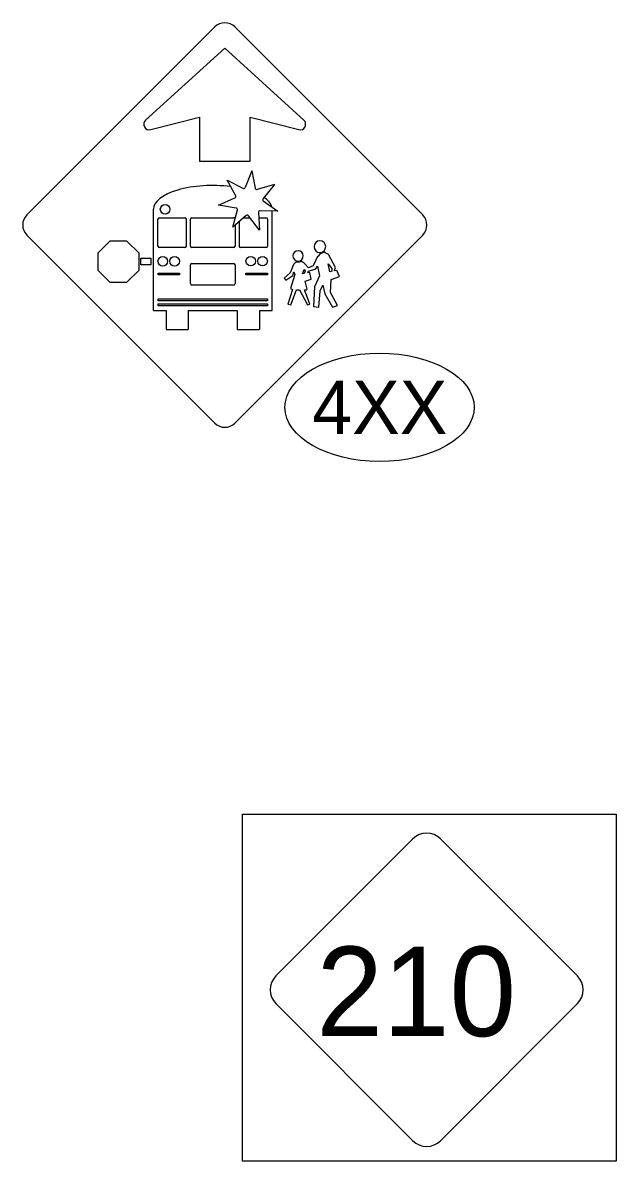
# Model space of a CAD drawing. Extents: x 1977705 to 1981198, y 827296 to 829291.
# Drawn here: x 1979110.5 to 1979241.2, y 827983.6 to 828234.2 of the extents above; entities that cross this region are included whole.
import ezdxf

# ---------------------------------------------------------------- set-up
doc = ezdxf.new("R2010")
doc.units = 0
doc.layers.add('Default', color=7, linetype='Continuous')
doc.layers.add('Level 15', color=7, linetype='Continuous')

msp = doc.modelspace()

# ---------------------------------------------------------------- linework, layer by layer
at = {"layer": 'Default'}
for p, q in [((1979172.67, 828212.53), (1979172.67, 828212.53)), ((1979160.92, 828201.62), (1979159.46, 828197.96)), ((1979160.92, 828201.62), (1979161.69, 828197.81)), ((1979157.38, 828196.13), (1979155.48, 828199.59)), ((1979155.48, 828199.59), (1979158.98, 828197.78)), ((1979165.95, 828198.6), (1979162.13, 828197.54)), ((1979165.95, 828198.6), (1979163.4, 828195.52)), ((1979153.62, 828194.04), (1979157.22, 828195.65)), ((1979157.49, 828193.44), (1979153.62, 828194.04)), ((1979163.47, 828195.02), (1979166.68, 828192.74)), ((1979139.26, 828170.89), (1979139.26, 828193.18)), ((1979140.61, 828191.3), (1979146.18, 828191.3)), ((1979147.75, 828191.3), (1979156.9, 828191.3)), ((1979156.75, 828189.24), (1979157.77, 828193.01)), ((1979159.68, 828191.8), (1979156.75, 828189.24)), ((1979159.13, 828191.3), (1979160.52, 828191.3)), ((1979162.61, 828188.56), (1979160.18, 828191.75)), ((1979162.38, 828192.49), (1979162.61, 828188.56)), ((1979162.45, 828191.3), (1979164.04, 828191.3)), ((1979166.68, 828192.74), (1979162.74, 828192.86)), ((1979165.39, 828170.89), (1979165.39, 828192.79)), ((1979140.26, 828185.07), (1979140.26, 828190.96)), ((1979146.53, 828185.07), (1979146.53, 828190.96)), ((1979147.4, 828185.07), (1979147.4, 828190.96)), ((1979157.25, 828189.68), (1979157.25, 828185.07)), ((1979158.12, 828190.44), (1979158.12, 828185.07)), ((1979164.39, 828190.96), (1979164.39, 828185.07)), ((1979129.68, 828186.15), (1979127.02, 828183.49)), ((1979133.43, 828186.15), (1979129.68, 828186.15)), ((1979136.09, 828183.49), (1979133.43, 828186.15)), ((1979146.18, 828184.72), (1979140.61, 828184.72)), ((1979156.9, 828184.72), (1979147.75, 828184.72)), ((1979164.04, 828184.72), (1979158.47, 828184.72)), ((1979127.02, 828183.49), (1979127.02, 828179.74)), ((1979136.09, 828179.74), (1979136.09, 828183.49)), ((1979171.99, 828181.61), (1979171.99, 828181.61)), ((1979172.47, 828181.3), (1979172.47, 828181.3)), ((1979127.02, 828179.74), (1979129.68, 828177.09)), ((1979133.43, 828177.09), (1979136.09, 828179.74)), ((1979169.39, 828179.17), (1979169.39, 828179.17)), ((1979170.13, 828180.99), (1979170.13, 828180.99)), ((1979172.12, 828178.93), (1979172.12, 828178.93)), ((1979172.43, 828179.88), (1979172.43, 828179.88)), ((1979172.49, 828179.02), (1979172.49, 828179.02)), ((1979172.69, 828179.54), (1979172.69, 828179.54)), ((1979129.68, 828177.09), (1979133.43, 828177.09)), ((1979168.08, 828177.97), (1979168.08, 828177.97)), ((1979168.4, 828177.58), (1979168.4, 828177.58)), ((1979139.26, 828170.89), (1979142.05, 828170.89)), ((1979142.05, 828170.89), (1979142.05, 828166.71)), ((1979146.93, 828170.89), (1979146.93, 828166.71)), ((1979146.93, 828170.89), (1979157.72, 828170.89)), ((1979157.72, 828170.89), (1979157.72, 828166.71)), ((1979162.6, 828170.89), (1979162.6, 828166.71)), ((1979162.6, 828170.89), (1979165.39, 828170.89)), ((1979142.05, 828166.71), (1979146.93, 828166.71)), ((1979157.72, 828166.71), (1979162.6, 828166.71))]:
    msp.add_line(p, q, dxfattribs=at)
for points in [[(1979152.77, 828233.3), (1979111.39, 828191.92)], [(1979198.59, 828191.92), (1979157.21, 828233.3)], [(1979172.4, 828212.78), (1979154.98, 828228.63), (1979137.55, 828212.78)], [(1979138.67, 828210.69), (1979149.44, 828213.47), (1979149.44, 828203.79), (1979155.01, 828203.79)], [(1979155.01, 828203.79), (1979160.59, 828203.79), (1979160.59, 828213.45), (1979171.28, 828210.69)], [(1979111.39, 828187.48), (1979152.77, 828146.1)], [(1979157.21, 828146.1), (1979198.59, 828187.48)], [(1979170.71, 828181.62), (1979170.13, 828180.99), (1979169.39, 828179.17), (1979168.08, 828177.97), (1979168.4, 828177.58), (1979169.99, 828178.61), (1979170.21, 828179.42), (1979170.42, 828178.78), (1979169.43, 828175.7), (1979169.86, 828175.52), (1979168.84, 828172.25), (1979169.55, 828172.12), (1979170.81, 828175.43), (1979171.47, 828175.42), (1979173.18, 828172.1), (1979173.75, 828172.3), (1979172.57, 828175.42), (1979172.7, 828175.43), (1979172.81, 828175.43), (1979172.97, 828175.46), (1979173.08, 828175.51), (1979173.16, 828175.56), (1979172.65, 828177.37), (1979174.03, 828177.75), (1979173.7, 828179.28), (1979173.27, 828179.21), (1979173.4, 828179.53), (1979175, 828180.04), (1979175.38, 828180.67), (1979175.84, 828178.51), (1979174.74, 828176.11), (1979174.55, 828171.74), (1979175.71, 828171.59), (1979175.97, 828175.19), (1979176.58, 828176.48), (1979177, 828174.59), (1979178.72, 828171.59), (1979179.8, 828171.99), (1979178.26, 828174.82), (1979178.4, 828177.74), (1979180.22, 828178.36), (1979179.68, 828179.69), (1979179.17, 828179.63), (1979179.36, 828180.38), (1979177.84, 828183.19), (1979177.06, 828183.58), (1979177.02, 828183.83), (1979176.9, 828183.87)], [(1979147.75, 828181.25), (1979156.9, 828181.25)], [(1979171.99, 828181.61), (1979171.8, 828181.74)], [(1979175.95, 828183.49), (1979175.94, 828183.29), (1979175.44, 828182.8), (1979175.42, 828182.74), (1979174.42, 828180.69), (1979173.41, 828180.25), (1979172.61, 828181.17), (1979172.47, 828181.3), (1979171.99, 828181.61)], [(1979178.55, 828179.51), (1979178.13, 828179.4), (1979177.73, 828181.14), (1979178.59, 828180.11), (1979178.55, 828179.51)], [(1979147.4, 828176.81), (1979147.4, 828180.91)], [(1979157.25, 828180.91), (1979157.25, 828176.81)], [(1979172.49, 828179.02), (1979172.12, 828178.93), (1979172.43, 828179.88), (1979172.69, 828179.54), (1979172.49, 828179.02)], [(1979156.9, 828176.46), (1979147.75, 828176.46)]]:
    msp.add_lwpolyline(points, dxfattribs=at)
for points in [[(1979138.72, 828180.92), (1979136.51, 828180.92), (1979136.51, 828182.39), (1979138.72, 828182.39)], [(1979140.27, 828179.14), (1979145.02, 828179.14), (1979145.02, 828178.73), (1979140.27, 828178.73)], [(1979159.63, 828179.14), (1979164.38, 828179.14), (1979164.38, 828178.73), (1979159.63, 828178.73)], [(1979140.27, 828173.46), (1979164.38, 828173.46), (1979164.38, 828173.05), (1979140.27, 828173.05)], [(1979140.27, 828172.35), (1979164.38, 828172.35), (1979164.38, 828171.93), (1979140.27, 828171.93)]]:
    msp.add_lwpolyline(points, close=True, dxfattribs=at)
for centre in [(1979141.83, 828193.16), (1979141.31, 828181.71), (1979143.93, 828181.71), (1979160.7, 828181.74), (1979163.31, 828181.74)]:
    msp.add_circle(centre, 1.05, dxfattribs=at)
for centre, radius, start, end in [((1979154.99, 828231.08), 3.14, 45, 135), ((1979138.37, 828211.88), 1.22, 132.2977, 284.4727), ((1979171.58, 828211.88), 1.22, 255.5273, 47.702), ((1979157.08, 828195.97), 0.348, 294.0505, 28.8597), ((1979159.14, 828198.09), 0.348, 242.6236, 338.298), ((1979162.03, 828197.88), 0.348, 191.5346, 285.4779), ((1979163.67, 828195.3), 0.348, 140.3148, 234.6619), ((1979113.61, 828189.7), 3.14, 135, 225), ((1979140.61, 828190.96), 0.348, 90, 180), ((1979146.18, 828190.96), 0.348, 360, 90), ((1979147.75, 828190.96), 0.348, 90, 180), ((1979156.9, 828190.96), 0.348, 24.4568, 90), ((1979157.44, 828193.1), 0.348, 344.861, 81.276), ((1979159.91, 828191.54), 0.348, 37.2136, 131.2308), ((1979162.73, 828192.51), 0.348, 88.2351, 183.2328), ((1979164.04, 828190.96), 0.348, 360, 90), ((1979196.37, 828189.7), 3.14, 314.998, 45), ((1979175.93, 828184.94), 1.28, 360, 180), ((1979140.61, 828185.07), 0.348, 180, 270), ((1979146.18, 828185.07), 0.348, 270, 360), ((1979147.75, 828185.07), 0.348, 180, 270), ((1979156.9, 828185.07), 0.348, 270, 360), ((1979158.47, 828185.07), 0.348, 180, 270), ((1979164.04, 828185.07), 0.348, 270, 360), ((1979171.12, 828182.89), 1.14, 360, 180), ((1979175.93, 828184.94), 1.28, 180, 360), ((1979175.93, 828184.93), 1.44, 270.8077, 312.6802), ((1979147.75, 828180.91), 0.348, 90, 180), ((1979156.9, 828180.91), 0.348, 360, 90), ((1979171.12, 828182.89), 1.14, 180, 360), ((1979171.12, 828182.89), 1.33, 252.1121, 300.8936), ((1979147.75, 828176.81), 0.348, 180, 270), ((1979156.9, 828176.81), 0.348, 270, 360), ((1979154.99, 828148.32), 3.14, 224.998, 315)]:
    msp.add_arc(centre, radius, start, end, dxfattribs=at)
for start_param, end_param in [(1.265977, 3.141593), (0.098799, 0.527026)]:
    msp.add_ellipse((1979152.33, 828193.18), major_axis=(13.06, 0), ratio=0.399852, start_param=start_param, end_param=end_param, dxfattribs=at)
msp.add_ellipse((1979189.08, 828149.58), major_axis=(-20.85, 0), ratio=0.571429, dxfattribs=at)
at = {"layer": 'Level 15'}
for p, q in [((1979166.24, 828024.42), (1979196.4, 828054.61)), ((1979202.48, 828054.61), (1979232.67, 828024.42)), ((1979196.4, 827988.15), (1979166.24, 828018.33)), ((1979232.67, 828018.33), (1979202.48, 827988.15))]:
    msp.add_line(p, q, dxfattribs=at)
msp.add_lwpolyline([(1979158.85, 828060.06), (1979241.21, 828060.06), (1979241.21, 827983.64), (1979158.85, 827983.64)], close=True, dxfattribs=at)
for centre, start, end in [((1979199.45, 828051.55), 45, 135), ((1979169.28, 828021.38), 135, 225), ((1979229.62, 828021.38), 315, 45), ((1979199.45, 827991.2), 225, 315)]:
    msp.add_arc(centre, 4.3, start, end, dxfattribs=at)

# ---------------------------------------------------------------- texts
at = {"layer": 'Default'}
msp.add_text('4XX', height=11.77, rotation=360, dxfattribs=at).set_placement((1979174.27, 828143.69))
at = {"layer": 'Level 15'}
msp.add_text('210', height=19.709, dxfattribs=at).set_placement((1979175.17, 828011.17))

doc.saveas('drawing.dxf')
